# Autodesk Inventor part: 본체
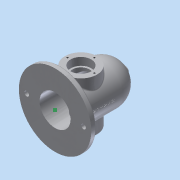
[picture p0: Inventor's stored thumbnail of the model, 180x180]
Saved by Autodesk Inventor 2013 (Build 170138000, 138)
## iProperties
Created: 2019-11
Part Number: 본체
Material: 알루미늄 6061
Document SubType Name: Modeling
Designer: Administrator
Density: 2.71 g/cm^3
Mass: 1110.43 g
Surface Area: 884.701 cm^2
Volume: 409.754 cm^3
Author: Administrator
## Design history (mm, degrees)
sketch "스케치1"
  geometry: 1 further point
sketch "스케치2"
  geometry: C1 r 70 at (0, 0); 1 further point
  constraints: 1 centre point, 1 coincident
  dimensions: "d0" = 140 diameter of C1
extrude "돌출1" new body sketch "스케치2" distance "d2" = 10; taper "d3" = 0 deg
sketch "스케치3"
  geometry: C1 r 70 at (0, 0) reference; C2 r 40 at (0, 0)
  constraints: 1 centre point, 1 coincident
  dimensions: "d4" = 80 diameter of C2
extrude "돌출2" join sketch "스케치3" distance "d6" = 80; taper "d7" = 0 deg
sketch "스케치4"
  geometry: L1 (0, 70)-(0, -70) reference; L2 (130, 0)-(50, 0); A1 r 40 centre (90, 0) between (130, 0) and (50, 0); 2 further points
  constraints: 2 end point, 2 point on circle, 1 centre point, 1 coincident, 1 perpendicular
  dimensions: "d8" = 90 distance from line of L1 point (90, 0); "d10" = 80 diameter of A1
revolve "회전1" sketch "스케치4" stored, may be unused: angle "d11" = 90 deg
sketch "스케치5"
  geometry: L1 (-70, 0)-(70, 0) reference; C1 r 31 at (0, 50); 2 further points
  constraints: 1 centre point, 1 coincident
  dimensions: "d12" = 50 distance from line of L1 point (0, 50); "d13" = 62 diameter of C1
extrude "돌출3" join sketch "스케치5" stored distance "d14" = 100; taper "d15" = 0 deg
node "작업 평면2"
sketch "스케치6"
  geometry: C1 r 7.5 at (0, 0); 1 further point
  constraints: 1 centre point, 1 coincident
  dimensions: "d18" = 15 diameter of C1
extrude "돌출4" join sketch "스케치6" stored distance "d20" = 100; taper "d21" = 0 deg
sketch "스케치7"
  geometry: C1 r 7.5 at (0, 0) reference; 1 further point
  constraints: 1 coincident
hole "구멍1" sketch "스케치7" at (0, 0) diameter "d22" = 5.188; stored, may be unused: countersink angle "d26" = 90 deg, drill point angle "d28" = 118 deg; dims "d23" = 6, "d24" = 4, "d25" = 2, "d27" = 8
fillet "모깎기1" dims "d29" = 3
sketch "스케치8"
  geometry: C1 r 31 at (0, 0) reference; C2 r 16.5 at (0, 0); 1 further point
  constraints: 1 centre point, 1 coincident
  dimensions: "d30" = 33 diameter of C2
extrude "돌출5" cut sketch "스케치8" distance "d32" = 100; taper "d33" = 0 deg
sketch "스케치9"
  geometry: C1 r 2.594 at (0, 0) reference; C2 r 70 at (0, 0) reference; C3 r 30 at (0, 0)
  constraints: 1 centre point, 1 coincident
  dimensions: "d34" = 60 diameter of C3
extrude "돌출6" cut sketch "스케치9" distance "d36" = 90; taper "d37" = 0 deg
sketch "스케치11"
  geometry: L1 (0, 70)-(0, -70) reference; L2 (60, 0)-(120, 0); A1 r 30 centre (90, 0) between (120, 0) and (60, 0); 2 further points
  constraints: 2 end point, 2 point on circle, 1 centre point, 1 coincident, 1 perpendicular
  dimensions: "d38" = 90 distance from line of L1 point (90, 0); "d39" = 60 diameter of A1
revolve "회전2" sketch "스케치11" stored, may be unused: angle "d40" = 90 deg
sketch "스케치12"
  geometry: C1 r 31 at (0, 0) reference; C2 r 20 at (0, 0); 1 further point
  constraints: 1 centre point, 1 coincident
  dimensions: "d41" = 40 diameter of C2
extrude "돌출7" cut sketch "스케치12" distance "d43" = 15; taper "d44" = 0 deg
sketch "스케치13"
  geometry: C1 r 31 at (0, 0) reference; C2 r 20 at (0, 0); 1 further point
  constraints: 1 centre point, 1 coincident
  dimensions: "d45" = 40 diameter of C2
extrude "돌출8" cut sketch "스케치13" distance "d47" = 15; taper "d48" = 0 deg
sketch "스케치14" dims "d49" = 52
  geometry: C1 r 31 at (0, 0) reference; C2 r 2 at (0, -26); 2 further points
  constraints: 2 vertical alignment, 1 centre point, 1 coincident, 2 other
  dimensions: "d51" = 4 diameter of C2
hole "구멍2" sketch "스케치14" at (0, -26) diameter "d52" = 3.242; stored, may be unused: countersink angle "d56" = 90 deg, drill point angle "d58" = 118 deg; dims "d53" = 8, "d54" = 4, "d55" = 2, "d57" = 10
sketch "스케치15" dims "d63" = 110
  geometry: C1 r 40 at (0, 0) reference; C2 r 70 at (0, 0) reference; C3 r 4.5 at (-55, 0); 1 further point
  constraints: 2 horizontal alignment, 1 centre point, 1 coincident, 2 other
  dimensions: "d62" = 9 diameter of C3
extrude "돌출9" cut sketch "스케치15" distance "d64" = 15; taper "d65" = 0 deg
node "작업 평면3"
sketch "스케치18"
  geometry: L1 (0, 70)-(0, -70) reference; 2 further points
  constraints: 1 horizontal alignment, 1 other
  dimensions: "d67" = 50 distance from line of L1 point (50, 0)
feature "엠보싱1" sketch "스케치18" dims "d12" = 50, "d13" = 62, "d68" = 0.5, "d69" = 0
fillet "모깎기2" dims "d70" = 3
fillet "모깎기3" dims "d71" = 3
fillet "모깎기4" dims "d72" = 3
fillet "모깎기5" dims "d73" = 0.3
node "솔리드1"
pattern_circular "원형 패턴1" dims angle "d60" = 360 deg
mirror "대칭1"
mirror "대칭2"
other parameters: "d17" = -135
